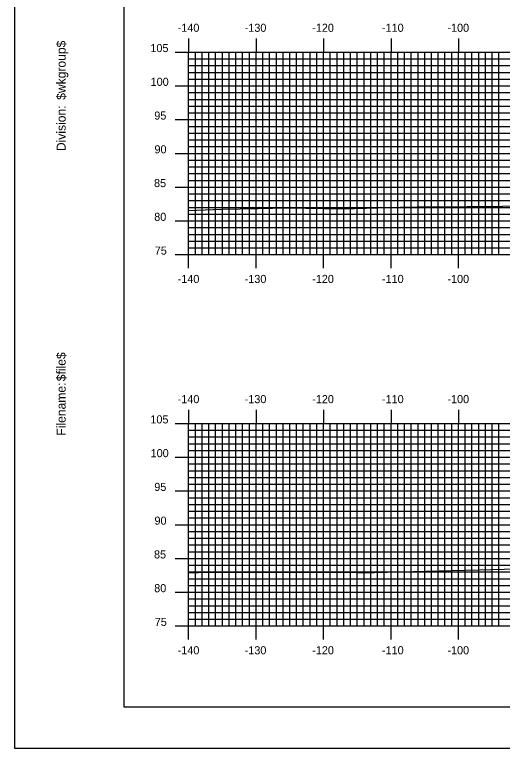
# Model space of a CAD drawing. Extents: x 2453 to 2796, y -1658 to -1438.
# Drawn here: x 2452.9 to 2525.2, y -1657.7 to -1549.1 of the extents above; entities that cross this region are included whole.
import ezdxf

# ---------------------------------------------------------------- set-up
doc = ezdxf.new("R2010")
doc.units = 0
for name, color, linetype in [('BORDER', 7, 'Continuous'), ('H_V ANNOTATION', 7, 'Continuous'), ('MAJOR', 7, 'Continuous'), ('MINOR', 7, 'Continuous'), ('PLOT BOUNDARY', 7, 'Continuous'), ('S_Roadway_Centerline', 7, 'Continuous')]:
    doc.layers.add(name, color=color, linetype=linetype)

msp = doc.modelspace()

# ---------------------------------------------------------------- linework, layer by layer
at = {"layer": 'BORDER'}
msp.add_lwpolyline([(2469.1, -1651.6), (2789.1, -1651.6), (2789.1, -1441.6), (2469.1, -1441.6)], close=True, dxfattribs=at)
at = {"layer": 'MAJOR'}
for p, q in [((2478.7, -1552.6), (2478.7, -1554.6)), ((2488.7, -1552.6), (2488.7, -1554.6)), ((2498.7, -1552.6), (2498.7, -1554.6)), ((2508.7, -1552.6), (2508.7, -1554.6)), ((2518.7, -1552.6), (2518.7, -1554.6)), ((2476.7, -1554.6), (2478.7, -1554.6)), ((2478.7, -1554.6), (2758.7, -1554.6)), ((2478.7, -1584.6), (2478.7, -1554.6)), ((2478.7, -1584.6), (2478.7, -1554.6)), ((2478.7, -1554.6), (2758.7, -1554.6)), ((2488.7, -1584.6), (2488.7, -1554.6)), ((2498.7, -1584.6), (2498.7, -1554.6)), ((2508.7, -1584.6), (2508.7, -1554.6)), ((2518.7, -1584.6), (2518.7, -1554.6)), ((2476.7, -1559.6), (2478.7, -1559.6)), ((2478.7, -1559.6), (2758.7, -1559.6)), ((2476.7, -1564.6), (2478.7, -1564.6)), ((2478.7, -1564.6), (2758.7, -1564.6)), ((2476.7, -1569.6), (2478.7, -1569.6)), ((2478.7, -1569.6), (2758.7, -1569.6)), ((2476.7, -1574.6), (2478.7, -1574.6)), ((2478.7, -1574.6), (2758.7, -1574.6)), ((2476.7, -1579.6), (2478.7, -1579.6)), ((2478.7, -1579.6), (2758.7, -1579.6)), ((2476.7, -1584.6), (2478.7, -1584.6)), ((2478.7, -1584.6), (2758.7, -1584.6)), ((2478.7, -1584.6), (2758.7, -1584.6)), ((2478.7, -1586.61), (2478.7, -1584.6)), ((2488.7, -1586.61), (2488.7, -1584.6)), ((2498.7, -1586.61), (2498.7, -1584.6)), ((2508.7, -1586.61), (2508.7, -1584.6)), ((2518.7, -1586.61), (2518.7, -1584.6)), ((2478.7, -1607.6), (2478.7, -1609.6)), ((2488.7, -1607.6), (2488.7, -1609.6)), ((2498.7, -1607.6), (2498.7, -1609.6)), ((2508.7, -1607.6), (2508.7, -1609.6)), ((2518.7, -1607.6), (2518.7, -1609.6)), ((2476.7, -1609.6), (2478.7, -1609.6)), ((2478.7, -1609.6), (2758.7, -1609.6)), ((2478.7, -1639.6), (2478.7, -1609.6)), ((2478.7, -1639.6), (2478.7, -1609.6)), ((2478.7, -1609.6), (2758.7, -1609.6)), ((2488.7, -1639.6), (2488.7, -1609.6)), ((2498.7, -1639.6), (2498.7, -1609.6)), ((2508.7, -1639.6), (2508.7, -1609.6)), ((2518.7, -1639.6), (2518.7, -1609.6)), ((2476.7, -1614.6), (2478.7, -1614.6)), ((2478.7, -1614.6), (2758.7, -1614.6)), ((2476.7, -1619.6), (2478.7, -1619.6)), ((2478.7, -1619.6), (2758.7, -1619.6)), ((2476.7, -1624.6), (2478.7, -1624.6)), ((2478.7, -1624.6), (2758.7, -1624.6)), ((2476.7, -1629.6), (2478.7, -1629.6)), ((2478.7, -1629.6), (2758.7, -1629.6)), ((2476.7, -1634.6), (2478.7, -1634.6)), ((2478.7, -1634.6), (2758.7, -1634.6)), ((2476.7, -1639.6), (2478.7, -1639.6)), ((2478.7, -1639.6), (2758.7, -1639.6)), ((2478.7, -1639.6), (2758.7, -1639.6)), ((2478.7, -1641.61), (2478.7, -1639.6)), ((2488.7, -1641.61), (2488.7, -1639.6)), ((2498.7, -1641.61), (2498.7, -1639.6)), ((2508.7, -1641.61), (2508.7, -1639.6)), ((2518.7, -1641.61), (2518.7, -1639.6))]:
    msp.add_line(p, q, dxfattribs=at)
at = {"layer": 'MINOR'}
for p, q in [((2479.7, -1584.6), (2479.7, -1554.6)), ((2480.7, -1584.6), (2480.7, -1554.6)), ((2481.7, -1584.6), (2481.7, -1554.6)), ((2482.7, -1584.6), (2482.7, -1554.6)), ((2483.7, -1584.6), (2483.7, -1554.6)), ((2484.7, -1584.6), (2484.7, -1554.6)), ((2485.7, -1584.6), (2485.7, -1554.6)), ((2486.7, -1584.6), (2486.7, -1554.6)), ((2487.7, -1584.6), (2487.7, -1554.6)), ((2489.7, -1584.6), (2489.7, -1554.6)), ((2490.7, -1584.6), (2490.7, -1554.6)), ((2491.7, -1584.6), (2491.7, -1554.6)), ((2492.7, -1584.6), (2492.7, -1554.6)), ((2493.7, -1584.6), (2493.7, -1554.6)), ((2494.7, -1584.6), (2494.7, -1554.6)), ((2495.7, -1584.6), (2495.7, -1554.6)), ((2496.7, -1584.6), (2496.7, -1554.6)), ((2497.7, -1584.6), (2497.7, -1554.6)), ((2499.7, -1584.6), (2499.7, -1554.6)), ((2500.7, -1584.6), (2500.7, -1554.6)), ((2501.7, -1584.6), (2501.7, -1554.6)), ((2502.7, -1584.6), (2502.7, -1554.6)), ((2503.7, -1584.6), (2503.7, -1554.6)), ((2504.7, -1584.6), (2504.7, -1554.6)), ((2505.7, -1584.6), (2505.7, -1554.6)), ((2506.7, -1584.6), (2506.7, -1554.6)), ((2507.7, -1584.6), (2507.7, -1554.6)), ((2509.7, -1584.6), (2509.7, -1554.6)), ((2510.7, -1584.6), (2510.7, -1554.6)), ((2511.7, -1584.6), (2511.7, -1554.6)), ((2512.7, -1584.6), (2512.7, -1554.6)), ((2513.7, -1584.6), (2513.7, -1554.6)), ((2514.7, -1584.6), (2514.7, -1554.6)), ((2515.7, -1584.6), (2515.7, -1554.6)), ((2516.7, -1584.6), (2516.7, -1554.6)), ((2517.7, -1584.6), (2517.7, -1554.6)), ((2519.7, -1584.6), (2519.7, -1554.6)), ((2520.7, -1584.6), (2520.7, -1554.6)), ((2521.7, -1584.6), (2521.7, -1554.6)), ((2522.7, -1584.6), (2522.7, -1554.6)), ((2523.7, -1584.6), (2523.7, -1554.6)), ((2524.7, -1584.6), (2524.7, -1554.6)), ((2478.7, -1555.6), (2758.7, -1555.6)), ((2478.7, -1555.6), (2480.7, -1555.6)), ((2478.7, -1556.6), (2758.7, -1556.6)), ((2478.7, -1556.6), (2480.7, -1556.6)), ((2478.7, -1557.6), (2758.7, -1557.6)), ((2478.7, -1557.6), (2480.7, -1557.6)), ((2478.7, -1558.6), (2758.7, -1558.6)), ((2478.7, -1558.6), (2480.7, -1558.6)), ((2478.7, -1560.6), (2758.7, -1560.6)), ((2478.7, -1560.6), (2480.7, -1560.6)), ((2478.7, -1561.6), (2758.7, -1561.6)), ((2478.7, -1561.6), (2480.7, -1561.6)), ((2478.7, -1562.6), (2758.7, -1562.6)), ((2478.7, -1562.6), (2480.7, -1562.6)), ((2478.7, -1563.6), (2758.7, -1563.6)), ((2478.7, -1563.6), (2480.7, -1563.6)), ((2478.7, -1565.6), (2758.7, -1565.6)), ((2478.7, -1565.6), (2480.7, -1565.6)), ((2478.7, -1566.6), (2758.7, -1566.6)), ((2478.7, -1566.6), (2480.7, -1566.6)), ((2478.7, -1567.6), (2758.7, -1567.6)), ((2478.7, -1567.6), (2480.7, -1567.6)), ((2478.7, -1568.6), (2758.7, -1568.6)), ((2478.7, -1568.6), (2480.7, -1568.6)), ((2478.7, -1570.6), (2758.7, -1570.6)), ((2478.7, -1570.6), (2480.7, -1570.6)), ((2478.7, -1571.6), (2758.7, -1571.6)), ((2478.7, -1571.6), (2480.7, -1571.6)), ((2478.7, -1572.6), (2758.7, -1572.6)), ((2478.7, -1572.6), (2480.7, -1572.6)), ((2478.7, -1573.6), (2758.7, -1573.6)), ((2478.7, -1573.6), (2480.7, -1573.6)), ((2478.7, -1575.6), (2758.7, -1575.6)), ((2478.7, -1575.6), (2480.7, -1575.6)), ((2478.7, -1576.6), (2758.7, -1576.6)), ((2478.7, -1576.6), (2480.7, -1576.6)), ((2478.7, -1577.6), (2758.7, -1577.6)), ((2478.7, -1577.6), (2480.7, -1577.6)), ((2478.7, -1578.6), (2758.7, -1578.6)), ((2478.7, -1578.6), (2480.7, -1578.6)), ((2478.7, -1580.6), (2758.7, -1580.6)), ((2478.7, -1580.6), (2480.7, -1580.6)), ((2478.7, -1581.6), (2758.7, -1581.6)), ((2478.7, -1581.6), (2480.7, -1581.6)), ((2478.7, -1582.6), (2758.7, -1582.6)), ((2478.7, -1582.6), (2480.7, -1582.6)), ((2478.7, -1583.6), (2758.7, -1583.6)), ((2478.7, -1583.6), (2480.7, -1583.6)), ((2479.7, -1639.6), (2479.7, -1609.6)), ((2480.7, -1639.6), (2480.7, -1609.6)), ((2481.7, -1639.6), (2481.7, -1609.6)), ((2482.7, -1639.6), (2482.7, -1609.6)), ((2483.7, -1639.6), (2483.7, -1609.6)), ((2484.7, -1639.6), (2484.7, -1609.6)), ((2485.7, -1639.6), (2485.7, -1609.6)), ((2486.7, -1639.6), (2486.7, -1609.6)), ((2487.7, -1639.6), (2487.7, -1609.6)), ((2489.7, -1639.6), (2489.7, -1609.6)), ((2490.7, -1639.6), (2490.7, -1609.6)), ((2491.7, -1639.6), (2491.7, -1609.6)), ((2492.7, -1639.6), (2492.7, -1609.6)), ((2493.7, -1639.6), (2493.7, -1609.6)), ((2494.7, -1639.6), (2494.7, -1609.6)), ((2495.7, -1639.6), (2495.7, -1609.6)), ((2496.7, -1639.6), (2496.7, -1609.6)), ((2497.7, -1639.6), (2497.7, -1609.6)), ((2499.7, -1639.6), (2499.7, -1609.6)), ((2500.7, -1639.6), (2500.7, -1609.6)), ((2501.7, -1639.6), (2501.7, -1609.6)), ((2502.7, -1639.6), (2502.7, -1609.6)), ((2503.7, -1639.6), (2503.7, -1609.6)), ((2504.7, -1639.6), (2504.7, -1609.6)), ((2505.7, -1639.6), (2505.7, -1609.6)), ((2506.7, -1639.6), (2506.7, -1609.6)), ((2507.7, -1639.6), (2507.7, -1609.6)), ((2509.7, -1639.6), (2509.7, -1609.6)), ((2510.7, -1639.6), (2510.7, -1609.6)), ((2511.7, -1639.6), (2511.7, -1609.6)), ((2512.7, -1639.6), (2512.7, -1609.6)), ((2513.7, -1639.6), (2513.7, -1609.6)), ((2514.7, -1639.6), (2514.7, -1609.6)), ((2515.7, -1639.6), (2515.7, -1609.6)), ((2516.7, -1639.6), (2516.7, -1609.6)), ((2517.7, -1639.6), (2517.7, -1609.6)), ((2519.7, -1639.6), (2519.7, -1609.6)), ((2520.7, -1639.6), (2520.7, -1609.6)), ((2521.7, -1639.6), (2521.7, -1609.6)), ((2522.7, -1639.6), (2522.7, -1609.6)), ((2523.7, -1639.6), (2523.7, -1609.6)), ((2524.7, -1639.6), (2524.7, -1609.6)), ((2478.7, -1610.6), (2758.7, -1610.6)), ((2478.7, -1610.6), (2480.7, -1610.6)), ((2478.7, -1611.6), (2758.7, -1611.6)), ((2478.7, -1611.6), (2480.7, -1611.6)), ((2478.7, -1612.6), (2758.7, -1612.6)), ((2478.7, -1612.6), (2480.7, -1612.6)), ((2478.7, -1613.6), (2758.7, -1613.6)), ((2478.7, -1613.6), (2480.7, -1613.6)), ((2478.7, -1615.6), (2758.7, -1615.6)), ((2478.7, -1615.6), (2480.7, -1615.6)), ((2478.7, -1616.6), (2758.7, -1616.6)), ((2478.7, -1616.6), (2480.7, -1616.6)), ((2478.7, -1617.6), (2758.7, -1617.6)), ((2478.7, -1617.6), (2480.7, -1617.6)), ((2478.7, -1618.6), (2758.7, -1618.6)), ((2478.7, -1618.6), (2480.7, -1618.6)), ((2478.7, -1620.6), (2758.7, -1620.6)), ((2478.7, -1620.6), (2480.7, -1620.6)), ((2478.7, -1621.6), (2758.7, -1621.6)), ((2478.7, -1621.6), (2480.7, -1621.6)), ((2478.7, -1622.6), (2758.7, -1622.6)), ((2478.7, -1622.6), (2480.7, -1622.6)), ((2478.7, -1623.6), (2758.7, -1623.6)), ((2478.7, -1623.6), (2480.7, -1623.6)), ((2478.7, -1625.6), (2758.7, -1625.6)), ((2478.7, -1625.6), (2480.7, -1625.6)), ((2478.7, -1626.6), (2758.7, -1626.6)), ((2478.7, -1626.6), (2480.7, -1626.6)), ((2478.7, -1627.6), (2758.7, -1627.6)), ((2478.7, -1627.6), (2480.7, -1627.6)), ((2478.7, -1628.6), (2758.7, -1628.6)), ((2478.7, -1628.6), (2480.7, -1628.6)), ((2478.7, -1630.6), (2758.7, -1630.6)), ((2478.7, -1630.6), (2480.7, -1630.6)), ((2478.7, -1631.6), (2758.7, -1631.6)), ((2478.7, -1631.6), (2480.7, -1631.6)), ((2478.7, -1632.6), (2758.7, -1632.6)), ((2478.7, -1632.6), (2480.7, -1632.6)), ((2478.7, -1633.6), (2758.7, -1633.6)), ((2478.7, -1633.6), (2480.7, -1633.6)), ((2478.7, -1635.6), (2758.7, -1635.6)), ((2478.7, -1635.6), (2480.7, -1635.6)), ((2478.7, -1636.6), (2758.7, -1636.6)), ((2478.7, -1636.6), (2480.7, -1636.6)), ((2478.7, -1637.6), (2758.7, -1637.6)), ((2478.7, -1637.6), (2480.7, -1637.6)), ((2478.7, -1638.6), (2758.7, -1638.6)), ((2478.7, -1638.6), (2480.7, -1638.6))]:
    msp.add_line(p, q, dxfattribs=at)
at = {"layer": 'PLOT BOUNDARY'}
msp.add_lwpolyline([(2452.91, -1657.72), (2792.91, -1657.72), (2792.91, -1437.72), (2452.91, -1437.72)], close=True, dxfattribs=at)
at = {"layer": 'S_Roadway_Centerline'}
for points in [[(2478.7, -1578.07), (2483.61, -1577.88), (2489.03, -1577.79), (2493.33, -1577.67), (2501.63, -1577.8), (2510.08, -1577.55), (2512.57, -1577.5), (2514.74, -1577.5), (2535.7, -1577.31), (2536.46, -1577.31), (2547.46, -1576.85), (2558.14, -1576.82), (2560.25, -1576.87), (2562.41, -1576.87), (2578.48, -1577.01), (2581.98, -1577.05), (2586.67, -1577.12), (2606.39, -1577.25)], [(2478.7, -1631.71), (2481.71, -1631.64), (2482.19, -1631.63), (2482.64, -1631.61), (2503.71, -1631.68), (2506.22, -1631.7), (2525.49, -1631.19), (2527.81, -1631.16), (2538.29, -1631.12), (2549.31, -1631.11), (2550.35, -1631.09), (2551.43, -1631.05), (2562.17, -1630.42), (2573.02, -1630.17), (2585.95, -1630.01), (2596.6, -1629.72), (2597.11, -1629.73)]]:
    msp.add_lwpolyline(points, dxfattribs=at)

# ---------------------------------------------------------------- texts
at = {"layer": 'BORDER'}
for s, p in [('$wkgroup$', (2460.47, -1561.67)), ('Division:', (2460.47, -1569.27)), ('$file$', (2460.47, -1603.35)), ('Filename:', (2460.47, -1611.41))]:
    msp.add_text(s, height=1.339, rotation=90, dxfattribs=at).set_placement(p)
at = {"layer": 'H_V ANNOTATION'}
for s, p in [('-140', (2477.08, -1551.6)), ('-130', (2487.01, -1551.6)), ('-120', (2497.02, -1551.6)), ('-110', (2507.36, -1551.6)), ('-100', (2517.06, -1551.6)), ('105', (2473.03, -1554.6)), ('100', (2473.07, -1559.6)), ('95', (2473.61, -1564.6)), ('90', (2473.64, -1569.6)), ('85', (2473.57, -1574.6)), ('80', (2473.6, -1579.6)), ('75', (2473.68, -1584.6)), ('-140', (2477.08, -1588.8)), ('-130', (2487.01, -1588.8)), ('-120', (2497.02, -1588.8)), ('-110', (2507.36, -1588.8)), ('-100', (2517.06, -1588.8)), ('-140', (2477.08, -1606.6)), ('-130', (2487.01, -1606.6)), ('-120', (2497.02, -1606.6)), ('-110', (2507.36, -1606.6)), ('-100', (2517.06, -1606.6)), ('105', (2473.03, -1609.6)), ('100', (2473.07, -1614.6)), ('95', (2473.61, -1619.6)), ('90', (2473.64, -1624.6)), ('85', (2473.57, -1629.6)), ('80', (2473.6, -1634.6)), ('75', (2473.68, -1639.6)), ('-140', (2477.08, -1643.8)), ('-130', (2487.01, -1643.8)), ('-120', (2497.02, -1643.8)), ('-110', (2507.36, -1643.8)), ('-100', (2517.06, -1643.8))]:
    msp.add_text(s, height=1.2, dxfattribs=at).set_placement(p)
at = {"layer": 'MAJOR'}
for p in [(2478.69, -1584.6), (2478.69, -1639.6)]:
    msp.add_text('-', height=0.012, dxfattribs=at).set_placement(p)

doc.saveas('drawing.dxf')
